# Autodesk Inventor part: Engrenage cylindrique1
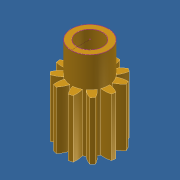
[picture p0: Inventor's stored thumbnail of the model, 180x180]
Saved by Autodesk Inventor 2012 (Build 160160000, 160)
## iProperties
Created: 2011-10
Part Number: Engrenage cylindrique1
Material: Laiton (jaune doux)
Document SubType Name: Modeling
Designer: Laur
Mass: 0.174951 g
Surface Area: 1.0732 cm^2
Volume: 0.0206553 cm^3
Density: 8.47 g/cm^3
CustomPartVersion: 1
Author: Laur
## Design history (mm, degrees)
sketch "Sketch1"
  geometry: C1 r 1.663 at (0, 0)
  constraints: 1 centre point
  dimensions: "d0" = 3.325 diameter of C1 (= da_da)
extrude "Extrusion1" new body sketch "Sketch1" distance "d1" = 3.4 (= da_b); taper "d2" = 0 deg
workplane "Work Plane2"
sketch "Sketch2"
  geometry: C1 r 1.663 at (0, 0) reference; C2 r 1.375 at (0, 0)
  constraints: 1 centre point, 1 coincident
  dimensions: "d3" = 2.75 diameter of C2 (= da_dw)
extrude_surface "ExtrusionSrf1" sketch "Sketch2" dims "d4" = 10, "d5" = 0
workplane "Work Plane8"
workplane "Work Plane9"
feature "Engrenage cylindrique" dims "da_b" = 3.4, "da_d" = 2.75, "da_aw" = 6, "da_da" = 3.325, "da_df" = 2.2, "da_dw" = 2.75, angle "da_beta" = 0 deg, "da_lefttooth" = 0, "da_righttooth" = 0
sketch "Esquisse3"
  geometry: C1 r 0.75 at (0, 0) reference
extrude "Extrusion2" cut sketch "Esquisse3" stored distance "d49" = 10; taper "d50" = 0 deg
sketch "Esquisse4"
  geometry: C1 r 0.75 at (0, 0) reference; C2 r 1.1 at (0, 0); A1 r 1.663 centre (0, 0) between (-0.797, 1.459) and (-0.996, 1.331) reference
  constraints: 1 centre point, 1 coincident
  dimensions: "d51" = 2.2 diameter of C2
extrude "Extrusion3" join sketch "Esquisse4" distance "d52" = 1.8; taper "d53" = 0 deg
sketch "Esquisse5"
  geometry: L1 (0, 0)-(0, -1.1); C1 r 0.75 at (0, 0) reference
  constraints: 2 end point, 1 vertical, 1 vertical alignment, 1 other
node "Solide1"
node "Corps solides"
node "Corps surfaciques"
body "Srf1"
node "Référence1"
other parameters: "d16" = 6 (= da_aw), "d17" = 0, "d34" = 2.85599 (computed from da_z), "d39" = 0, "d41" = 0, "d43" = 6 (= da_aw), "d46" = 6 (= da_aw), "d47" = 0, "d48" = 0
